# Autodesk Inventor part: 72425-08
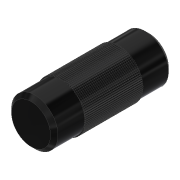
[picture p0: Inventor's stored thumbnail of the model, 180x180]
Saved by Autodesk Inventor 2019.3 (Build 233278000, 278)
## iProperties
Created: 2012-10
Part Number: 72425-08
Material: Ogólny
Document SubType Name: Modeling
Designer: CADENGINEERING4
Density: 1 g/cm^3
Appearance: Gładki — czarny
Author: CADENGINEERING4
Revision Number: ÈÎºÎ
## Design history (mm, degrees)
feature "ÊäÈë1"
node "Bryła1"
